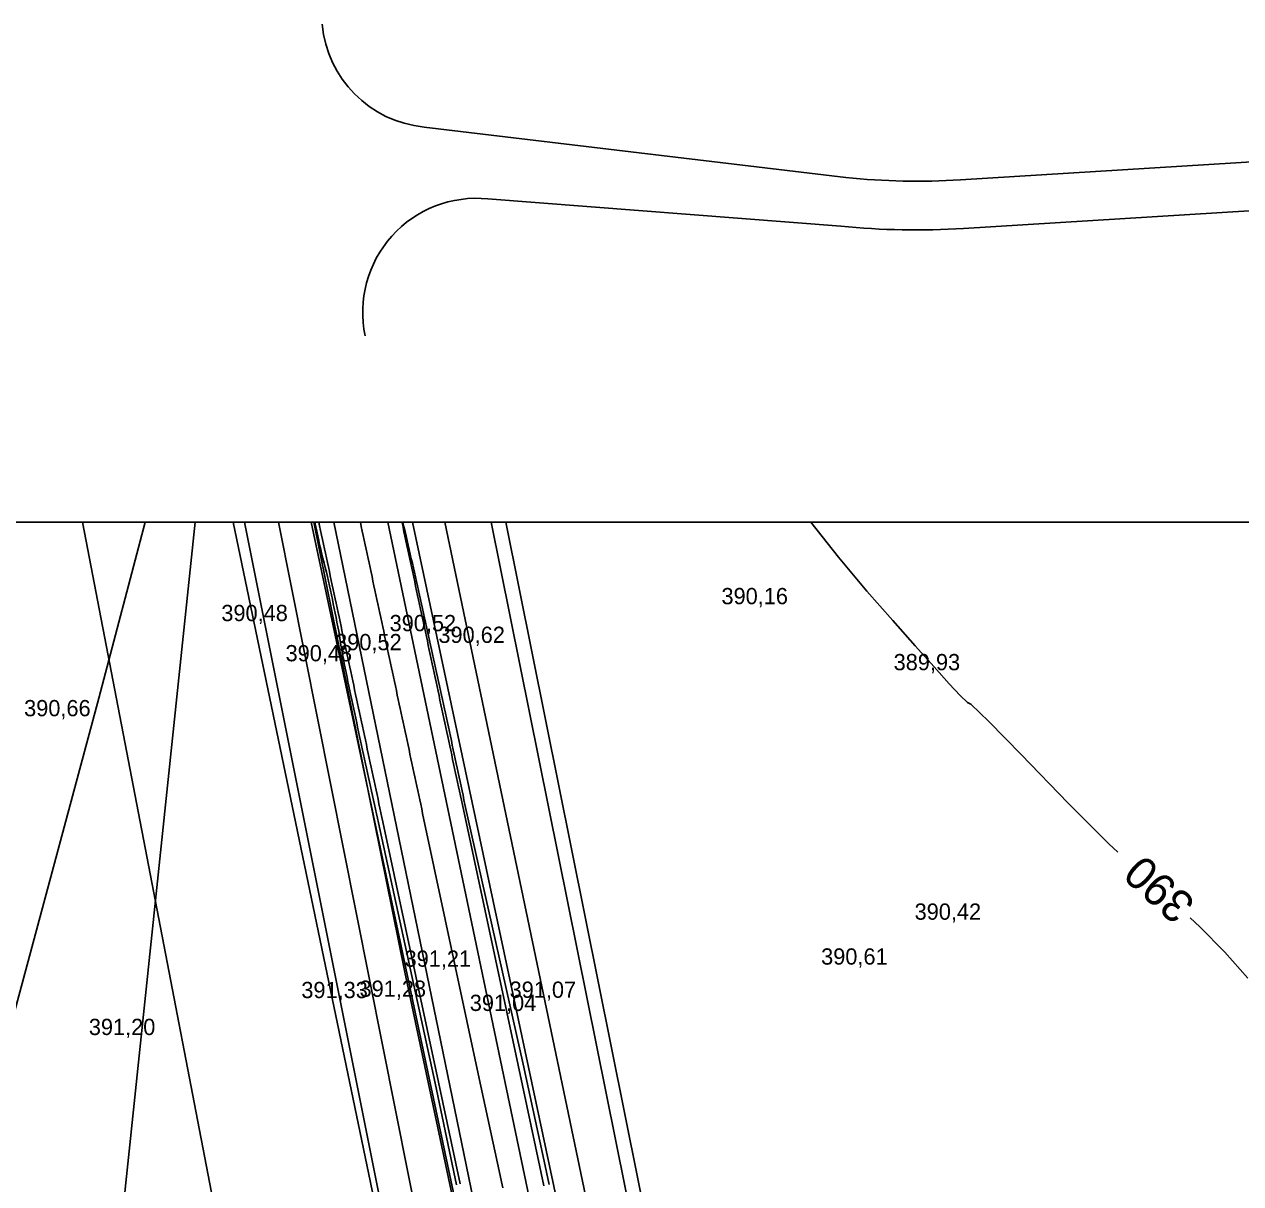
# Model space of a CAD drawing. Extents: x -574342 to -507939, y -1144044 to -1123894.
# Drawn here: x -508564.2 to -508489.4, y -1142888.4 to -1142817.1 of the extents above; entities that cross this region are included whole.
import ezdxf

# ---------------------------------------------------------------- set-up
doc = ezdxf.new("R2010")
doc.units = 0
for name, color, linetype in [('01_PARCELY_NAVRH_PC', 7, 'Continuous'), ('01_PARCELY_NAVRH_ŽP', 7, 'Continuous'), ('07_VODOVOD', 7, 'Continuous'), ('1000', 7, 'Continuous'), ('21', 7, 'Continuous'), ('37', 7, 'Continuous'), ('42', 7, 'Continuous'), ('55', 7, 'Continuous'), ('cesty', 7, 'Continuous'), ('Level 1', 7, 'Continuous'), ('Level 255', 7, 'Continuous'), ('VRST HL', 7, 'Continuous'), ('VRST POPIS', 7, 'Continuous')]:
    doc.layers.add(name, color=color, linetype=linetype)

msp = doc.modelspace()

# ---------------------------------------------------------------- linework, layer by layer
at = {"layer": '01_PARCELY_NAVRH_PC'}
msp.add_line((-508540.355, -1142847.7), (-508546.584, -1142847.7), dxfattribs=at)
msp.add_lwpolyline([(-508546.584, -1142847.7), (-508527.76, -1142936.34), (-508528.85, -1142941.84), (-508524.62, -1142962.65), (-508521.23, -1142966.97), (-508506.03, -1143042.25), (-508499.26, -1143041.98), (-508503.94, -1143018.7), (-508540.355, -1142847.7)], dxfattribs=at)
at = {"layer": '01_PARCELY_NAVRH_ŽP'}
for p, q in [((-508546.584, -1142847.7), (-508551.381, -1142847.7)), ((-508534.61, -1142847.7), (-508540.355, -1142847.7))]:
    msp.add_line(p, q, dxfattribs=at)
for points in [[(-508551.381, -1142847.7), (-508513, -1143032.18), (-508513.37, -1143051.16), (-508506.03, -1143042.25), (-508521.23, -1142966.97), (-508524.62, -1142962.65), (-508528.85, -1142941.84), (-508527.76, -1142936.34), (-508546.584, -1142847.7)], [(-508540.355, -1142847.7), (-508503.94, -1143018.7), (-508499.26, -1143041.98), (-508491.15, -1143065.29), (-508474.05, -1143124.14), (-508467.92, -1143139.18), (-508459.97, -1143152.33), (-508456.09, -1143158.71), (-508451.57, -1143168.14), (-508437.66, -1143207.58), (-508425.52, -1143241.92), (-508422.7, -1143249.88), (-508420.04, -1143252.1), (-508417.38, -1143252.95), (-508415.56, -1143252.78), (-508448.24, -1143160.16), (-508453.75, -1143145.01), (-508465.11, -1143123.03), (-508471.48, -1143106.99), (-508484.55, -1143061.98), (-508495.62, -1143031.06), (-508523.23, -1142904.28), (-508534.61, -1142847.7)]]:
    msp.add_lwpolyline(points, dxfattribs=at)
at = {"layer": '07_VODOVOD'}
for points in [[(-508866.763, -1143717.727), (-508837.79, -1143676.63), (-508822.73, -1143660.02), (-508794.64, -1143626.63), (-508794.19, -1143624.78), (-508778.48, -1143555.56), (-508751.62, -1143450.6), (-508717.96, -1143351.78), (-508693.81, -1143277.97), (-508673.43, -1143219.17), (-508660.38, -1143175.54), (-508652.67, -1143151.05), (-508650.03, -1143144), (-508640.33, -1143129.73), (-508639.81, -1143128.82), (-508635.48, -1143117.64), (-508605.2, -1143027.99), (-508590.53, -1142975.09), (-508573.99, -1142911.58), (-508559.64, -1142858.51), (-508556.791, -1142847.7)], [(-508656.802, -1143831.742), (-508553.726, -1142847.7)], [(-508640.05, -1143130.18), (-508637.48, -1143128.83), (-508626.48, -1143135.95), (-508617.09, -1143140.73), (-508602.61, -1143146.08), (-508586.87, -1143149.65), (-508578.03, -1143148.66), (-508571.02, -1143145.86), (-508562.51, -1143139.92), (-508546.01, -1143124.95), (-508535.68, -1143117.17), (-508526.75, -1143109.24), (-508521.13, -1143103.37), (-508515.47, -1143095.19), (-508511.95, -1143085.3), (-508511.14, -1143074.49), (-508510.31, -1143059.6), (-508507.36, -1143039.1), (-508508.06, -1143029.96), (-508510.42, -1143015.75), (-508519.77, -1142974.08), (-508526.08, -1142944.88), (-508540.82, -1142875.36), (-508546.434, -1142847.7)]]:
    msp.add_lwpolyline(points, dxfattribs=at)
at = {"layer": '1000'}
for points in [[(-508546.362, -1142847.7), (-508546.304, -1142847.976), (-508546.245, -1142848.256), (-508546.186, -1142848.536), (-508546.127, -1142848.816), (-508546.068, -1142849.096), (-508546.005, -1142849.375), (-508545.935, -1142849.653), (-508545.866, -1142849.931), (-508545.796, -1142850.209), (-508545.727, -1142850.487), (-508545.657, -1142850.765), (-508545.587, -1142851.043), (-508545.517, -1142851.32), (-508545.453, -1142851.6), (-508545.397, -1142851.881), (-508545.341, -1142852.161), (-508545.285, -1142852.442), (-508545.228, -1142852.723), (-508545.172, -1142853.003), (-508545.115, -1142853.284), (-508545.059, -1142853.565), (-508545.002, -1142853.845), (-508544.945, -1142854.126), (-508544.888, -1142854.407), (-508544.845, -1142854.69), (-508544.802, -1142854.974), (-508544.759, -1142855.257), (-508544.712, -1142855.54), (-508544.661, -1142855.822), (-508544.61, -1142856.104), (-508544.56, -1142856.386), (-508544.504, -1142856.667), (-508544.445, -1142856.947), (-508544.386, -1142857.227), (-508544.327, -1142857.507), (-508544.268, -1142857.787), (-508544.209, -1142858.067), (-508544.149, -1142858.348), (-508544.09, -1142858.628), (-508544.03, -1142858.908), (-508543.971, -1142859.188), (-508543.911, -1142859.468), (-508543.851, -1142859.748), (-508543.791, -1142860.028), (-508543.731, -1142860.308), (-508543.671, -1142860.588), (-508543.611, -1142860.867), (-508543.551, -1142861.147), (-508543.49, -1142861.427), (-508543.43, -1142861.707), (-508543.369, -1142861.987), (-508543.308, -1142862.267), (-508543.248, -1142862.546), (-508543.187, -1142862.826), (-508543.126, -1142863.106), (-508543.065, -1142863.386), (-508543.004, -1142863.665), (-508542.942, -1142863.945), (-508542.881, -1142864.225), (-508542.82, -1142864.504), (-508542.758, -1142864.784), (-508542.697, -1142865.064), (-508542.635, -1142865.343), (-508542.574, -1142865.623), (-508542.512, -1142865.902), (-508542.45, -1142866.182), (-508538.971, -1142882.183), (-508537.655, -1142888.435)], [(-508546.119, -1142847.7), (-508546.071, -1142847.926), (-508546.011, -1142848.206), (-508545.951, -1142848.486), (-508545.891, -1142848.766), (-508545.832, -1142849.046), (-508545.772, -1142849.326), (-508545.712, -1142849.606), (-508545.652, -1142849.886), (-508545.592, -1142850.166), (-508545.532, -1142850.445), (-508545.472, -1142850.725), (-508545.412, -1142851.005), (-508545.353, -1142851.285), (-508545.293, -1142851.565), (-508545.233, -1142851.845), (-508545.173, -1142852.125), (-508545.113, -1142852.405), (-508545.053, -1142852.685), (-508544.993, -1142852.965), (-508544.933, -1142853.245), (-508544.874, -1142853.525), (-508544.814, -1142853.805), (-508544.754, -1142854.085), (-508544.694, -1142854.365), (-508544.634, -1142854.645), (-508544.574, -1142854.925), (-508544.514, -1142855.205), (-508544.454, -1142855.485), (-508544.395, -1142855.765), (-508544.335, -1142856.045), (-508544.275, -1142856.325), (-508544.215, -1142856.605), (-508544.155, -1142856.885), (-508544.095, -1142857.165), (-508544.035, -1142857.445), (-508543.975, -1142857.725), (-508543.916, -1142858.005), (-508543.856, -1142858.285), (-508543.796, -1142858.565), (-508543.736, -1142858.845), (-508543.676, -1142859.125), (-508543.616, -1142859.405), (-508543.556, -1142859.685), (-508543.496, -1142859.965), (-508543.437, -1142860.245), (-508543.377, -1142860.525), (-508543.317, -1142860.805), (-508543.257, -1142861.085), (-508543.197, -1142861.364), (-508543.137, -1142861.644), (-508543.077, -1142861.924), (-508543.017, -1142862.204), (-508542.958, -1142862.484), (-508542.898, -1142862.764), (-508542.838, -1142863.044), (-508542.778, -1142863.324), (-508542.718, -1142863.604), (-508542.658, -1142863.884), (-508542.598, -1142864.164), (-508542.538, -1142864.444), (-508542.479, -1142864.724), (-508542.419, -1142865.004), (-508542.359, -1142865.284), (-508542.299, -1142865.564), (-508542.239, -1142865.844), (-508542.179, -1142866.124), (-508538.755, -1142882.137), (-508537.419, -1142888.385)], [(-508541.006, -1142847.7), (-508541.002, -1142847.72), (-508540.942, -1142848), (-508540.882, -1142848.28), (-508540.822, -1142848.56), (-508540.763, -1142848.84), (-508540.703, -1142849.12), (-508540.643, -1142849.4), (-508540.583, -1142849.68), (-508540.523, -1142849.96), (-508540.463, -1142850.24), (-508540.403, -1142850.52), (-508540.343, -1142850.8), (-508540.284, -1142851.08), (-508540.224, -1142851.36), (-508540.164, -1142851.64), (-508540.104, -1142851.92), (-508540.044, -1142852.2), (-508539.984, -1142852.48), (-508539.924, -1142852.76), (-508539.864, -1142853.04), (-508539.805, -1142853.319), (-508539.745, -1142853.599), (-508539.685, -1142853.879), (-508539.625, -1142854.159), (-508539.565, -1142854.439), (-508539.505, -1142854.719), (-508539.445, -1142854.999), (-508539.385, -1142855.279), (-508539.326, -1142855.559), (-508539.266, -1142855.839), (-508539.206, -1142856.119), (-508539.146, -1142856.399), (-508539.086, -1142856.679), (-508539.026, -1142856.959), (-508538.966, -1142857.239), (-508538.906, -1142857.519), (-508538.847, -1142857.799), (-508538.787, -1142858.079), (-508538.727, -1142858.359), (-508538.667, -1142858.639), (-508538.607, -1142858.919), (-508538.547, -1142859.199), (-508538.487, -1142859.479), (-508538.427, -1142859.759), (-508538.368, -1142860.039), (-508538.308, -1142860.319), (-508538.248, -1142860.599), (-508538.188, -1142860.879), (-508538.128, -1142861.159), (-508538.068, -1142861.439), (-508538.008, -1142861.719), (-508537.948, -1142861.999), (-508537.889, -1142862.279), (-508537.829, -1142862.559), (-508537.769, -1142862.839), (-508537.709, -1142863.119), (-508537.649, -1142863.399), (-508537.589, -1142863.679), (-508537.529, -1142863.958), (-508537.469, -1142864.238), (-508537.41, -1142864.518), (-508537.35, -1142864.798), (-508537.29, -1142865.078), (-508533.865, -1142881.091), (-508532.529, -1142887.339), (-508532.447, -1142887.725), (-508532.364, -1142888.111), (-508532.282, -1142888.497)], [(-508540.948, -1142847.7), (-508540.946, -1142847.708), (-508540.881, -1142847.987), (-508540.817, -1142848.266), (-508540.752, -1142848.545), (-508540.688, -1142848.824), (-508540.624, -1142849.103), (-508540.559, -1142849.382), (-508540.495, -1142849.661), (-508540.431, -1142849.94), (-508540.367, -1142850.219), (-508540.304, -1142850.498), (-508540.24, -1142850.778), (-508540.176, -1142851.057), (-508540.113, -1142851.336), (-508540.05, -1142851.615), (-508539.988, -1142851.895), (-508539.926, -1142852.174), (-508539.864, -1142852.454), (-508539.803, -1142852.734), (-508539.741, -1142853.013), (-508539.68, -1142853.293), (-508539.619, -1142853.572), (-508539.557, -1142853.852), (-508539.496, -1142854.132), (-508539.435, -1142854.412), (-508539.374, -1142854.691), (-508539.313, -1142854.971), (-508539.254, -1142855.251), (-508539.197, -1142855.532), (-508539.135, -1142855.811), (-508539.073, -1142856.091), (-508539.01, -1142856.37), (-508538.948, -1142856.65), (-508538.886, -1142856.929), (-508538.825, -1142857.209), (-508538.763, -1142857.488), (-508538.701, -1142857.768), (-508538.64, -1142858.048), (-508538.578, -1142858.327), (-508538.517, -1142858.607), (-508538.456, -1142858.887), (-508538.394, -1142859.166), (-508538.333, -1142859.446), (-508538.272, -1142859.726), (-508538.212, -1142860.005), (-508538.151, -1142860.285), (-508538.09, -1142860.565), (-508538.03, -1142860.845), (-508537.969, -1142861.125), (-508537.909, -1142861.405), (-508537.848, -1142861.685), (-508537.788, -1142861.964), (-508537.728, -1142862.244), (-508537.668, -1142862.524), (-508537.608, -1142862.804), (-508537.549, -1142863.084), (-508537.489, -1142863.364), (-508537.429, -1142863.644), (-508537.37, -1142863.924), (-508537.311, -1142864.204), (-508537.251, -1142864.485), (-508537.192, -1142864.765), (-508537.133, -1142865.045), (-508533.55, -1142881.024), (-508532.206, -1142887.27), (-508532.123, -1142887.656), (-508532.04, -1142888.042), (-508531.957, -1142888.427)]]:
    msp.add_lwpolyline(points, dxfattribs=at)
at = {"layer": '21'}
msp.add_lwpolyline([(-508543.563, -1142847.7), (-508543.507, -1142847.963), (-508543.447, -1142848.243), (-508543.387, -1142848.523), (-508543.327, -1142848.803), (-508543.267, -1142849.083), (-508543.207, -1142849.363), (-508543.147, -1142849.643), (-508543.088, -1142849.923), (-508543.028, -1142850.203), (-508542.968, -1142850.483), (-508542.908, -1142850.763), (-508542.848, -1142851.043), (-508542.788, -1142851.323), (-508542.728, -1142851.603), (-508542.668, -1142851.882), (-508542.609, -1142852.162), (-508542.549, -1142852.442), (-508542.489, -1142852.722), (-508542.429, -1142853.002), (-508542.369, -1142853.282), (-508542.309, -1142853.562), (-508542.249, -1142853.842), (-508542.189, -1142854.122), (-508542.13, -1142854.402), (-508542.07, -1142854.682), (-508542.01, -1142854.962), (-508541.95, -1142855.242), (-508541.89, -1142855.522), (-508541.83, -1142855.802), (-508541.77, -1142856.082), (-508541.71, -1142856.362), (-508541.651, -1142856.642), (-508541.591, -1142856.922), (-508541.531, -1142857.202), (-508541.471, -1142857.482), (-508541.411, -1142857.762), (-508541.351, -1142858.042), (-508541.291, -1142858.322), (-508541.231, -1142858.602), (-508541.172, -1142858.882), (-508541.112, -1142859.162), (-508541.052, -1142859.442), (-508540.992, -1142859.722), (-508540.932, -1142860.002), (-508540.872, -1142860.282), (-508540.812, -1142860.562), (-508540.752, -1142860.842), (-508540.693, -1142861.122), (-508540.633, -1142861.402), (-508540.573, -1142861.682), (-508540.513, -1142861.962), (-508540.453, -1142862.242), (-508540.393, -1142862.521), (-508540.333, -1142862.801), (-508540.273, -1142863.081), (-508540.214, -1142863.361), (-508540.154, -1142863.641), (-508540.094, -1142863.921), (-508540.034, -1142864.201), (-508539.974, -1142864.481), (-508539.914, -1142864.761), (-508539.854, -1142865.041), (-508539.794, -1142865.321), (-508539.735, -1142865.601), (-508536.31, -1142881.614), (-508534.974, -1142887.862), (-508534.891, -1142888.248), (-508534.809, -1142888.634)], dxfattribs=at)
at = {"layer": '37'}
for points in [[(-508511.59, -1143124.92), (-508509.54, -1143119.35), (-508506.51, -1143105.44), (-508506, -1143084.25), (-508505.31, -1143056.58), (-508505.39, -1143050.71), (-508505.49, -1143042.55), (-508509.4, -1143015.37), (-508521.08, -1142962.59), (-508532.6, -1142908.81), (-508545.204, -1142847.7)], [(-508511.59, -1143124.92), (-508509.54, -1143119.35), (-508506.51, -1143105.44), (-508506, -1143084.25), (-508505.31, -1143056.58), (-508505.39, -1143050.71), (-508505.49, -1143042.55), (-508509.4, -1143015.37), (-508521.08, -1142962.59), (-508532.6, -1142908.81), (-508545.204, -1142847.7)], [(-508541.866, -1142847.7), (-508529.22, -1142908.11), (-508517.67, -1142961.7), (-508506.14, -1143014.46), (-508500.54, -1143041.74), (-508495.34, -1143058.46)], [(-508541.866, -1142847.7), (-508529.22, -1142908.11), (-508517.67, -1142961.7), (-508506.14, -1143014.46), (-508500.54, -1143041.74), (-508495.34, -1143058.46)]]:
    msp.add_lwpolyline(points, dxfattribs=at)
at = {"layer": '42'}
for points in [[(-508560.651, -1142847.7), (-508548.46, -1142911.06), (-508536.86, -1142963.87), (-508529.29, -1143000.8), (-508523.32, -1143047.2)], [(-508560.651, -1142847.7), (-508548.46, -1142911.06), (-508536.86, -1142963.87), (-508529.29, -1143000.8), (-508523.32, -1143047.2)], [(-508510.77, -1143053.59), (-508510.65, -1143044.07), (-508514.85, -1143017.75), (-508526.24, -1142963.32), (-508538.39, -1142909.19), (-508550.685, -1142847.7)], [(-508510.77, -1143053.59), (-508510.65, -1143044.07), (-508514.85, -1143017.75), (-508526.24, -1142963.32), (-508538.39, -1142909.19), (-508550.685, -1142847.7)], [(-508445.89, -1143059.01), (-508479.63, -1143062.18), (-508484.42, -1143059.76), (-508487.39, -1143055.01), (-508499.96, -1143010.2), (-508511.4, -1142962.16), (-508523.74, -1142906.21), (-508535.517, -1142847.7)], [(-508445.89, -1143059.01), (-508479.63, -1143062.18), (-508484.42, -1143059.76), (-508487.39, -1143055.01), (-508499.96, -1143010.2), (-508511.4, -1142962.16), (-508523.74, -1142906.21), (-508535.517, -1142847.7)]]:
    msp.add_lwpolyline(points, dxfattribs=at)
at = {"layer": '55'}
for points in [[(-508548.593, -1142847.7), (-508536.61, -1142907.95), (-508524.27, -1142963.1), (-508513.79, -1143010.01), (-508509.84, -1143035.05), (-508508.31, -1143060.76)], [(-508548.593, -1142847.7), (-508536.61, -1142907.95), (-508524.27, -1142963.1), (-508513.79, -1143010.01), (-508509.84, -1143035.05), (-508508.31, -1143060.76)], [(-508492.58, -1143052.86), (-508498.99, -1143029.87), (-508513.85, -1142963.71), (-508525.48, -1142909.41), (-508538.364, -1142847.7)], [(-508492.58, -1143052.86), (-508498.99, -1143029.87), (-508513.85, -1142963.71), (-508525.48, -1142909.41), (-508538.364, -1142847.7)]]:
    msp.add_lwpolyline(points, dxfattribs=at)
at = {"layer": 'cesty'}
for p, q in [((-508539.647, -1142823.402), (-508513.709, -1142826.512)), ((-508535.722, -1142827.817), (-508514.009, -1142829.497))]:
    msp.add_line(p, q, dxfattribs=at)
for points in [[(-508506.662, -1142826.646), (-508483.082, -1142825.182), (-508452.763, -1142824.165)], [(-508506.476, -1142829.64), (-508482.938, -1142828.178), (-508452.662, -1142827.163)]]:
    msp.add_lwpolyline(points, dxfattribs=at)
for centre, radius, start, end in [((-508538.947, -1142816.437), 7, 185.31558, 264.26016), ((-508509.359, -1142783.23), 43.5, 264.26016, 273.55418), ((-508536.422, -1142834.782), 7, 84.26016, 191.94506), ((-508509.359, -1142783.23), 46.5, 264.26016, 273.55418)]:
    msp.add_arc(centre, radius, start, end, dxfattribs=at)
at = {"layer": 'Level 1'}
msp.add_lwpolyline([(-508026.763, -1142847.7), (-508026.763, -1144035.7), (-508866.763, -1144035.7), (-508866.763, -1142847.7)], close=True, dxfattribs=at)
at = {"layer": 'VRST HL'}
for points in [[(-508496.972, -1142867.992), (-508497.521, -1142867.477), (-508500.036, -1142864.972), (-508502.916, -1142861.982), (-508504.907, -1142859.952), (-508506.01, -1142858.882), (-508506.225, -1142858.773), (-508506.675, -1142858.355), (-508507.36, -1142857.63), (-508508.282, -1142856.597), (-508509.432, -1142855.303), (-508510.81, -1142853.749), (-508512.417, -1142851.933), (-508514.158, -1142849.846), (-508515.865, -1142847.7)], [(-508488.979, -1142875.728), (-508490.389, -1142874.144), (-508491.925, -1142872.577), (-508492.523, -1142872.019)]]:
    msp.add_lwpolyline(points, dxfattribs=at)

# ---------------------------------------------------------------- texts
at = {"layer": 'Level 255'}
for s, p in [('390,16', (-508521.355, -1142852.74)), ('390,48', (-508552.115, -1142853.78)), ('390,52', (-508541.765, -1142854.4)), ('390,52', (-508545.115, -1142855.57)), ('390,62', (-508538.765, -1142855.12)), ('390,48', (-508548.165, -1142856.25)), ('389,93', (-508510.765, -1142856.8)), ('390,66', (-508564.245, -1142859.63)), ('390,42', (-508509.475, -1142872.14)), ('391,21', (-508540.845, -1142875.03)), ('390,61', (-508515.225, -1142874.9)), ('391,33', (-508547.195, -1142876.96)), ('391,28', (-508543.615, -1142876.88)), ('391,07', (-508534.385, -1142876.94)), ('391,04', (-508536.835, -1142877.75)), ('391,20', (-508560.265, -1142879.23))]:
    msp.add_text(s, height=1, dxfattribs=at).set_placement(p)
at = {"layer": 'VRST POPIS'}
msp.add_text('390', height=2, rotation=137.85026, dxfattribs=at).set_placement((-508492.115, -1142871.04))

doc.saveas('drawing.dxf')
